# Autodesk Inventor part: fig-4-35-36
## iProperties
Created: 2005-12
Part Number: fig-4-35-36
Document SubType Name: Modeling
Designer: CADCIM
Density: 1 g/cm^3
Author: CADCIM
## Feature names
1. Extrusion1
